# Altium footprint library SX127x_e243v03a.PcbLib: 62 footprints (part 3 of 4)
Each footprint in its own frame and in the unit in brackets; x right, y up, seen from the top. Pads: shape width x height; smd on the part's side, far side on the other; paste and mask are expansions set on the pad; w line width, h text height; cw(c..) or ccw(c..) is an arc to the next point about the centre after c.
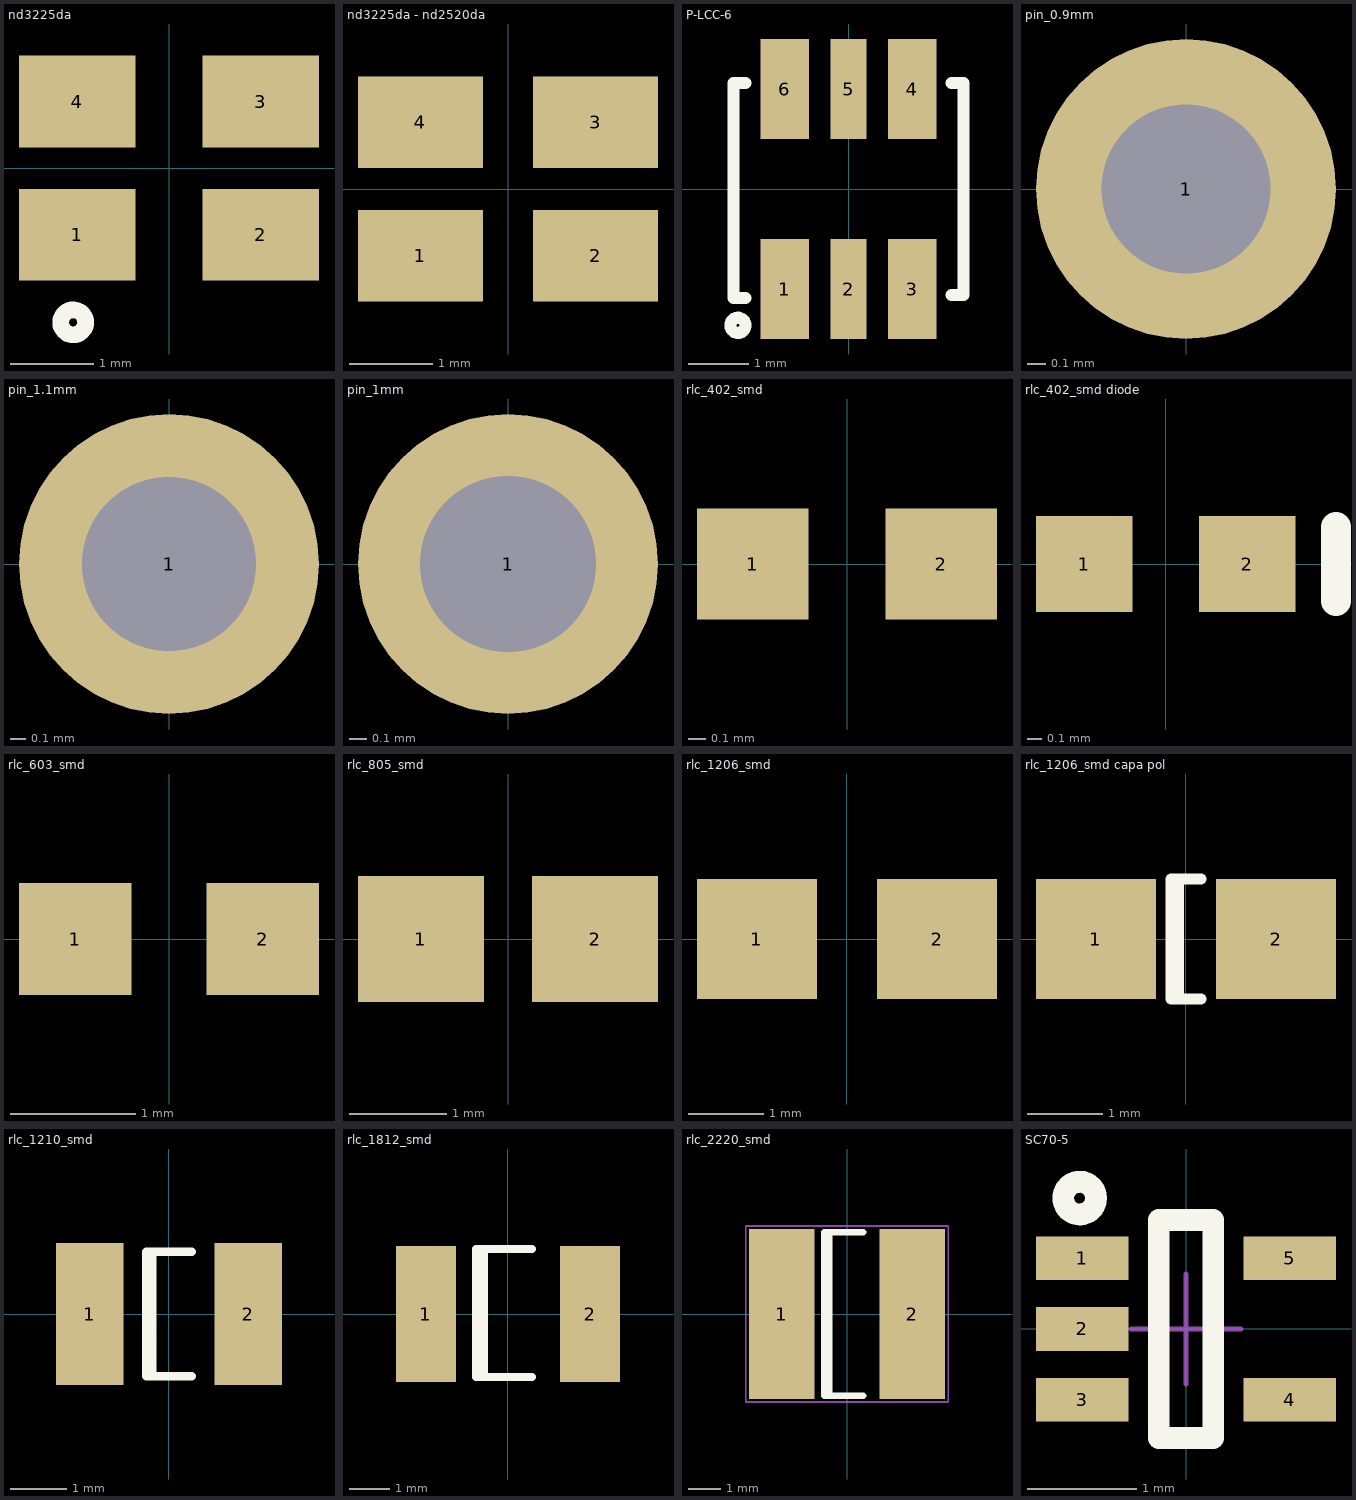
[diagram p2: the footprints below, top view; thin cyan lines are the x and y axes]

## nd3225da [mm] "Crystal SMD 3.2x2.5mm"
height 0.8
pads (4):
  rect 1.4x1.1 smd mask+0.05: 1(-1.1,-0.8) 2(1.1,-0.8) 3(1.1,0.8) 4(-1.1,0.8)
Top Overlay:
  circle w0.2: c-1.15,-1.85 r0.15
3D body: height 1, standoff 0, extent -1.6,-1.25 1.6,1.25

## nd3225da - nd2520da [mm] "Crystal SMD 3.2x2.5mm compatible with 2.5x2.0mm"
height 0.8
pads (4):
  rect 1.5x1.1 smd mask+0.05: 1(-1.05,-0.8) 2(1.05,-0.8) 3(1.05,0.8) 4(-1.05,0.8)
3D body: height 1, standoff 0, extent -1.6,-1.25 1.6,1.25

## P-LCC-6 [mm] "P-LCC-6 Package"
height 1.25
pads (6):
  rect 0.8x1.65 smd: 1(-1.05,-1.65) 3(1.05,-1.65) 4(1.05,1.65) 6(-1.05,1.65)
  rect 0.6x1.65 smd: 2(0,-1.65) 5(0,1.65)
Top Overlay:
  circle w0.2: c-1.825,-2.25 r0.125
  lines w0.2: -1.7,-1.8 -1.9,-1.8 -1.9,1.75 -1.7,1.75 ; 1.7,-1.75 1.9,-1.75 1.9,1.75 1.7,1.75

## pin_0.9mm [mm] "Generic Pin 0.9mm; 1 Lead"
height 1
pads (1):
  round 1.6 hole 0.9 mask+0.05: 1(0,0)

## pin_1.1mm [mm] "Generic Pin 1.1mm; 1 Lead"
height 1
pads (1):
  round 1.9 hole 1.1 mask+0.05: 1(0,0)

## pin_1mm [mm] "Generic Pin 1.1mm; 1 Lead"
height 1
pads (1):
  round 1.7 hole 1 paste+0 mask+0.05: 1(0,0)

## rlc_402_smd [mm] "Chip SMD component 402; Body 1.0 x 0.5 mm (LxW typ)"
height 0.8
pads (2):
  rect 0.65x0.65 smd mask+0.05: 1(-0.55,0) 2(0.55,0)

## rlc_402_smd diode [mm] "Chip SMD component 402; Body 1.0 x 0.5 mm (LxW typ)"
height 0.8
pads (2):
  rect 0.65x0.65 smd mask+0.05: 1(-0.55,0) 2(0.55,0)
Top Overlay:
  lines w0.2: 1.15,-0.25 1.15,0.25

## rlc_603_smd [mm] "Chip SMD component 603; Body 1.6 x 0.8mm (LxW typ)"
height 1
pads (2):
  rect 0.9x0.9 smd paste+0 mask+0.05: 1(-0.75,0) 2(0.75,0)

## rlc_805_smd [mm] "Chip SMD component 805; Body 2.0 x 1.25 mm (LxW typ)"
height 1.4
pads (2):
  rect 1.3x1.3 smd mask+0.05: 1(-0.9,0) 2(0.9,0)

## rlc_1206_smd [mm] "Chip SMD component 1206; Body 3.2 x 1.6 mm (LxW typ)"
height 2
pads (2):
  rect 1.6x1.6 smd mask+0.05: 1(-1.2,0) 2(1.2,0)

## rlc_1206_smd capa pol [mm] "Chip SMD component 1206; Body 3.2 x 1.6 mm (LxW typ)"
height 2
pads (2):
  rect 1.6x1.6 smd mask+0.05: 1(-1.2,0) 2(1.2,0)
Top Overlay:
  lines w0.15: -0.1,-0.8 -0.1,0.8 ; 0.2,-0.8 -0.2,-0.8 -0.2,0.8 0.2,0.8

## rlc_1210_smd [mm] "Chip SMD component 1210; Body 3.2 x 2.5 mm (LxW typ)"
height 2
pads (2):
  rect 1.2x2.5 smd mask+0.05: 1(-1.4,0) 2(1.4,0)
Top Overlay:
  lines w0.15: -0.3,-1.1 -0.3,1.1 ; 0.4,-1.1 -0.4,-1.1 -0.4,1.1 0.4,1.1

## rlc_1812_smd [mm] "Chip SMD component 1812; Body 4.5 x 3.2 mm (LxW typ)"
height 2.5
pads (2):
  rect 1.5x3.4 smd mask+0.05: 1(-2.05,0) 2(2.05,0)
Top Overlay:
  lines w0.2: -0.606,-1.579 -0.606,1.621 ; 0.604,-1.579 -0.796,-1.579 -0.796,1.621 0.604,1.621

## rlc_2220_smd [mm] "Chip SMD component ; Body 5.7 x 5.0 mm (LxW typ)"
height 5
pads (2):
  rect 2x5.2 smd mask+0.05: 1(-2,0) 2(2,0)
Top Overlay:
  lines w0.2: -0.55,-2.5 -0.55,2.5 ; 0.5,-2.5 -0.7,-2.5 -0.7,2.5 0.5,2.5
Mechanical 15:
  lines w0.05: -3.1,-2.7 -3.1,2.7 3.1,2.7 3.1,-2.7 -3.1,-2.7

## SC70-5 [mm] "SC70 5-Leads, Body 2.0x1.25mm, Pitch 0.65mm"
height 1.45
pads (5):
  rect 0.85x0.4 smd mask+0.05: 1(-0.95,0.65) 2(-0.95,0) 3(-0.95,-0.65) 4(0.95,-0.65) 5(0.95,0.65)
Top Overlay:
  circle w0.2: c-0.975,1.2 r0.15
  lines w0.2: -0.25,-1 0.25,-1 0.25,1 -0.25,1 -0.25,-1
Mechanical 15:
  lines w0.05: -0.5,0 0.5,0 ; 0,-0.5 0,0.5
3D body: height 1.45, standoff 0, extent -0.625,-1 0.625,1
